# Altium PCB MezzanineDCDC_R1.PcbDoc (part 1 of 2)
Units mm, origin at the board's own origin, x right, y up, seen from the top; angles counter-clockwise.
Board outline 70 x 70 mm, 4 copper layers (Top Layer, GND 1, Signal, Bottom Layer), stack 1.554 mm thick; 95 components, 53 nets, 436 pads, 382 vias.
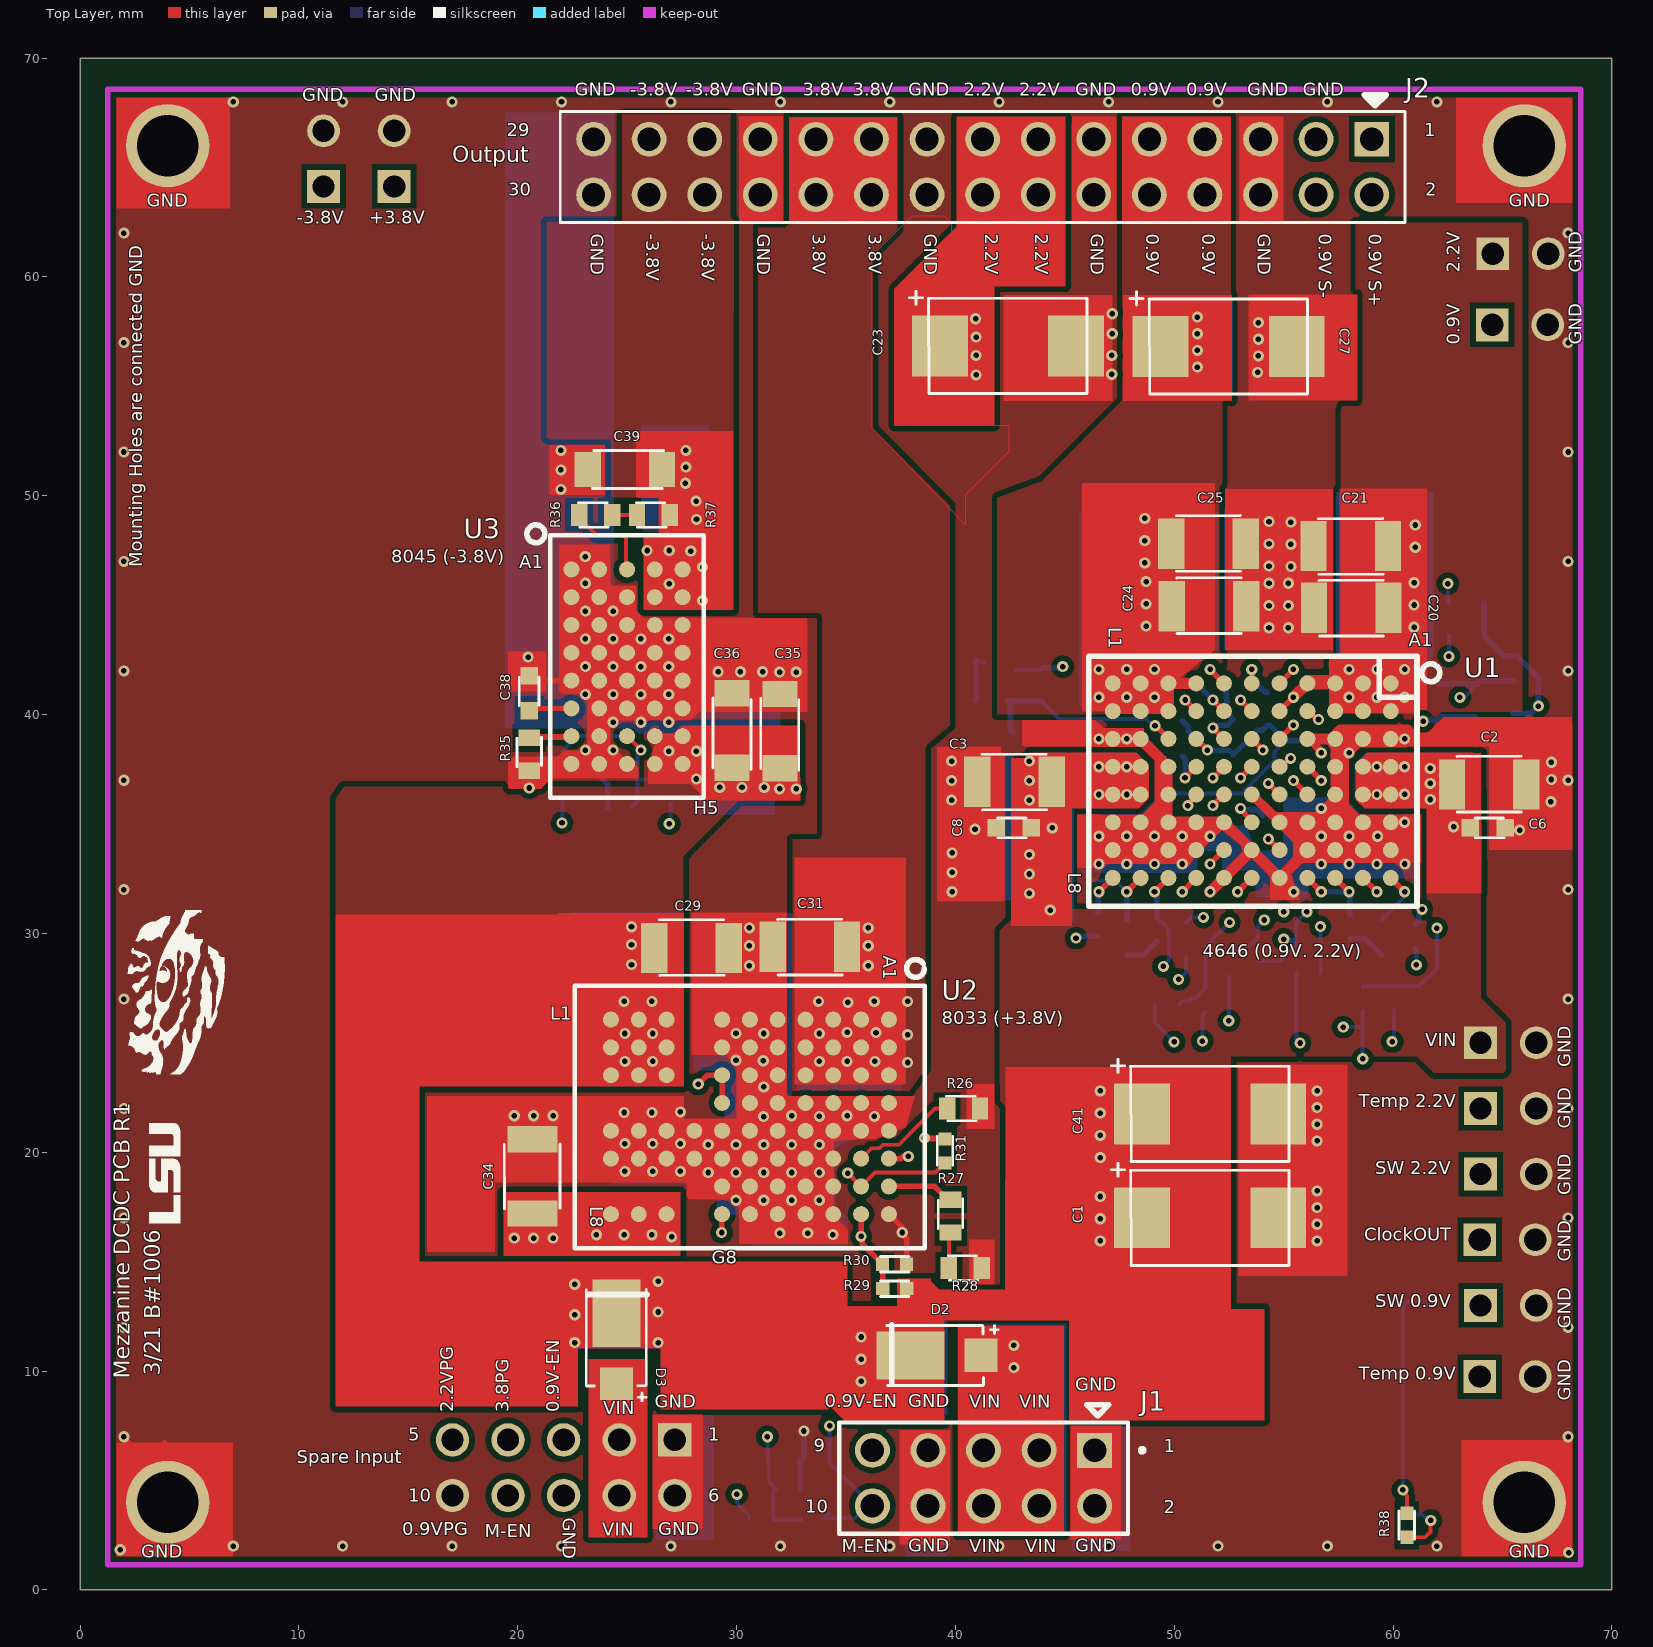
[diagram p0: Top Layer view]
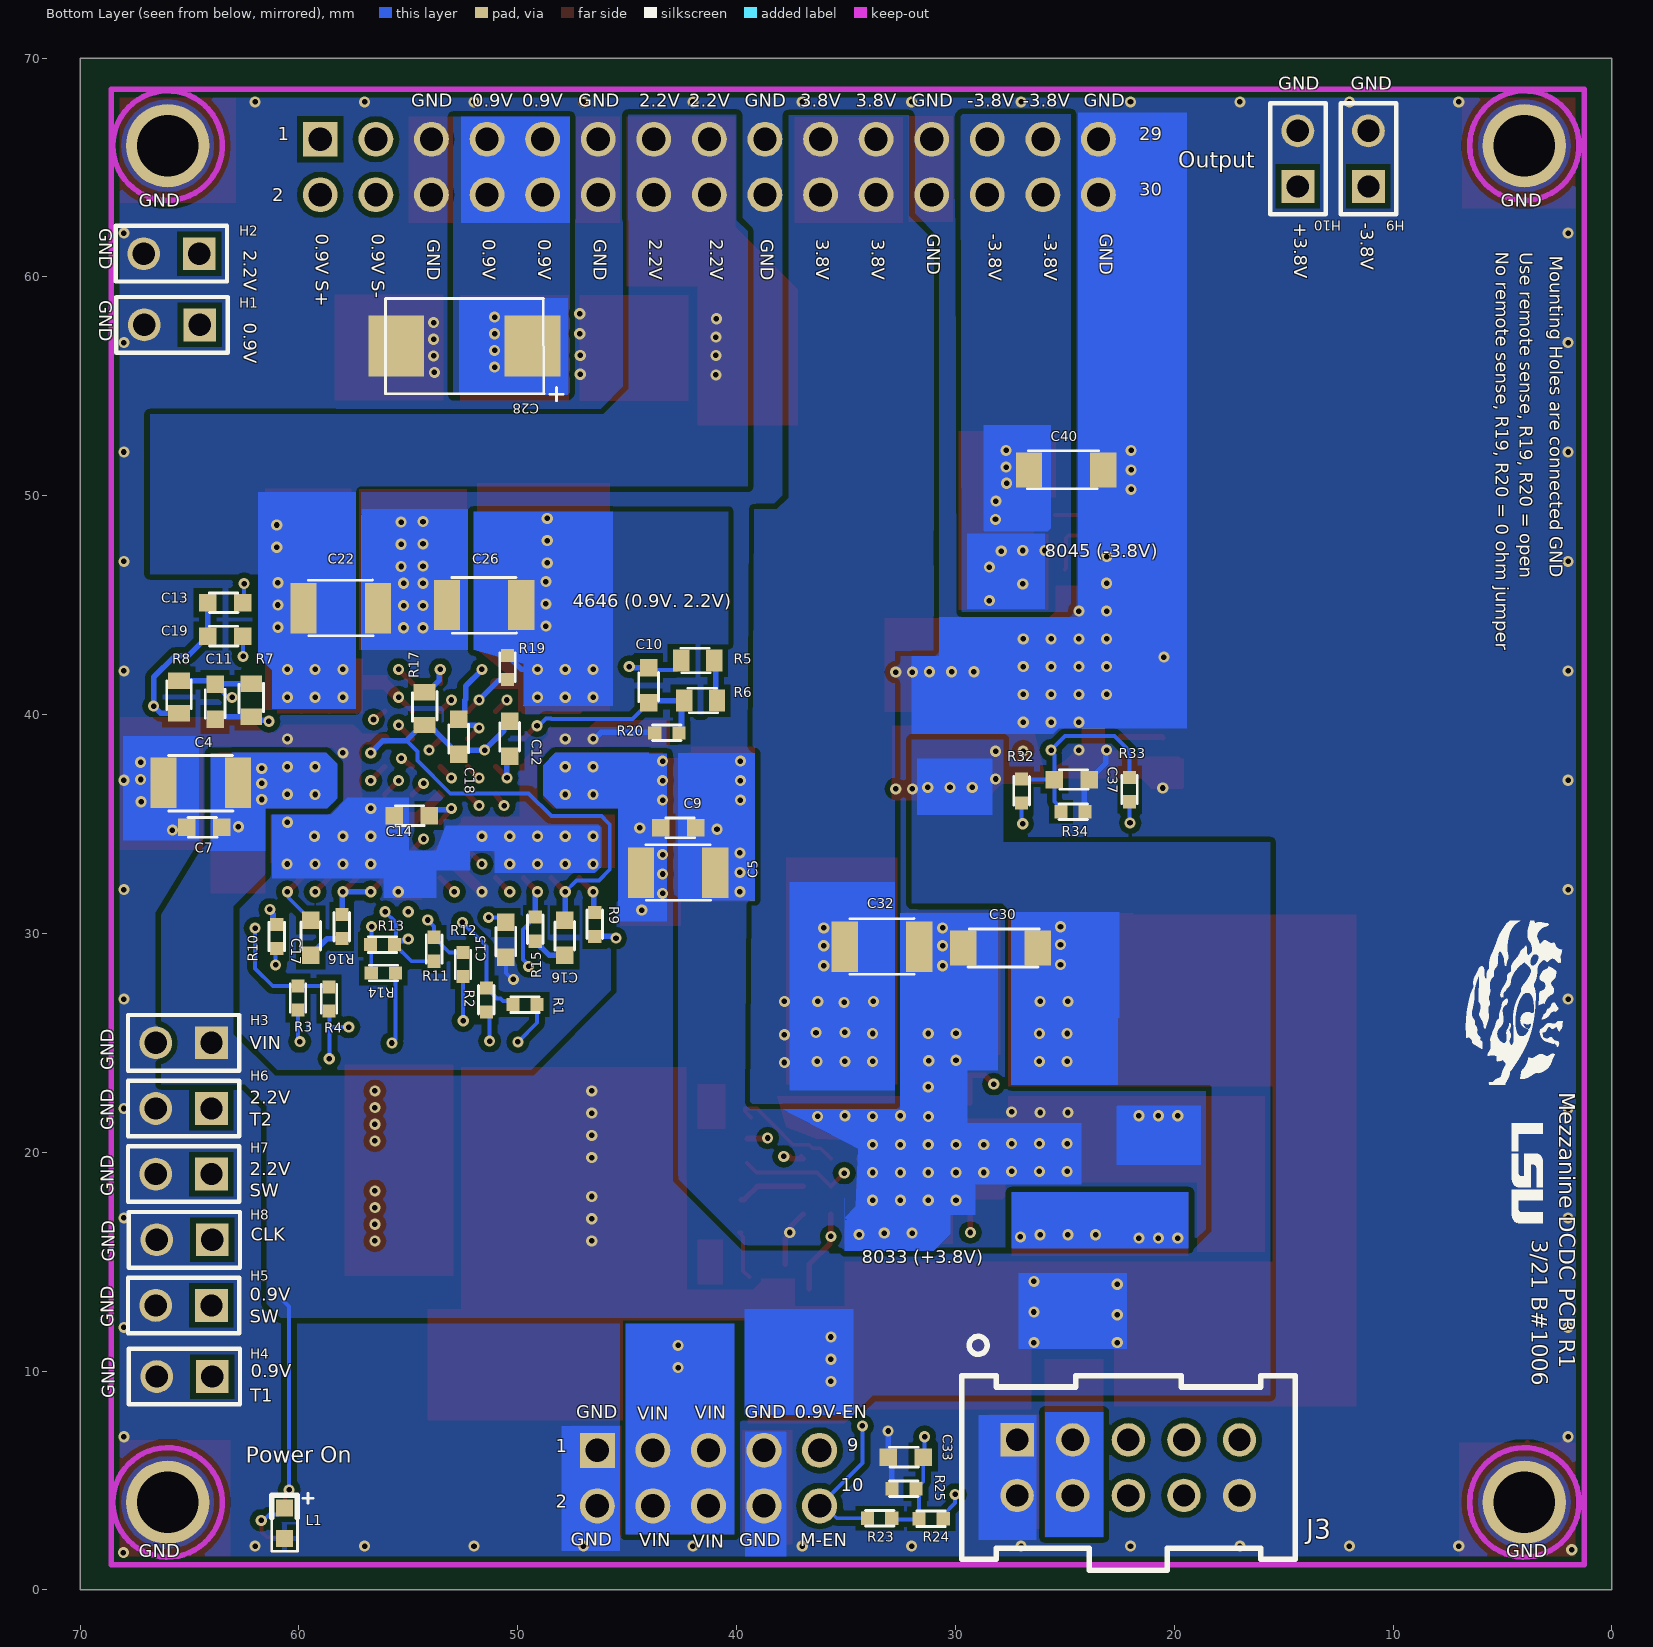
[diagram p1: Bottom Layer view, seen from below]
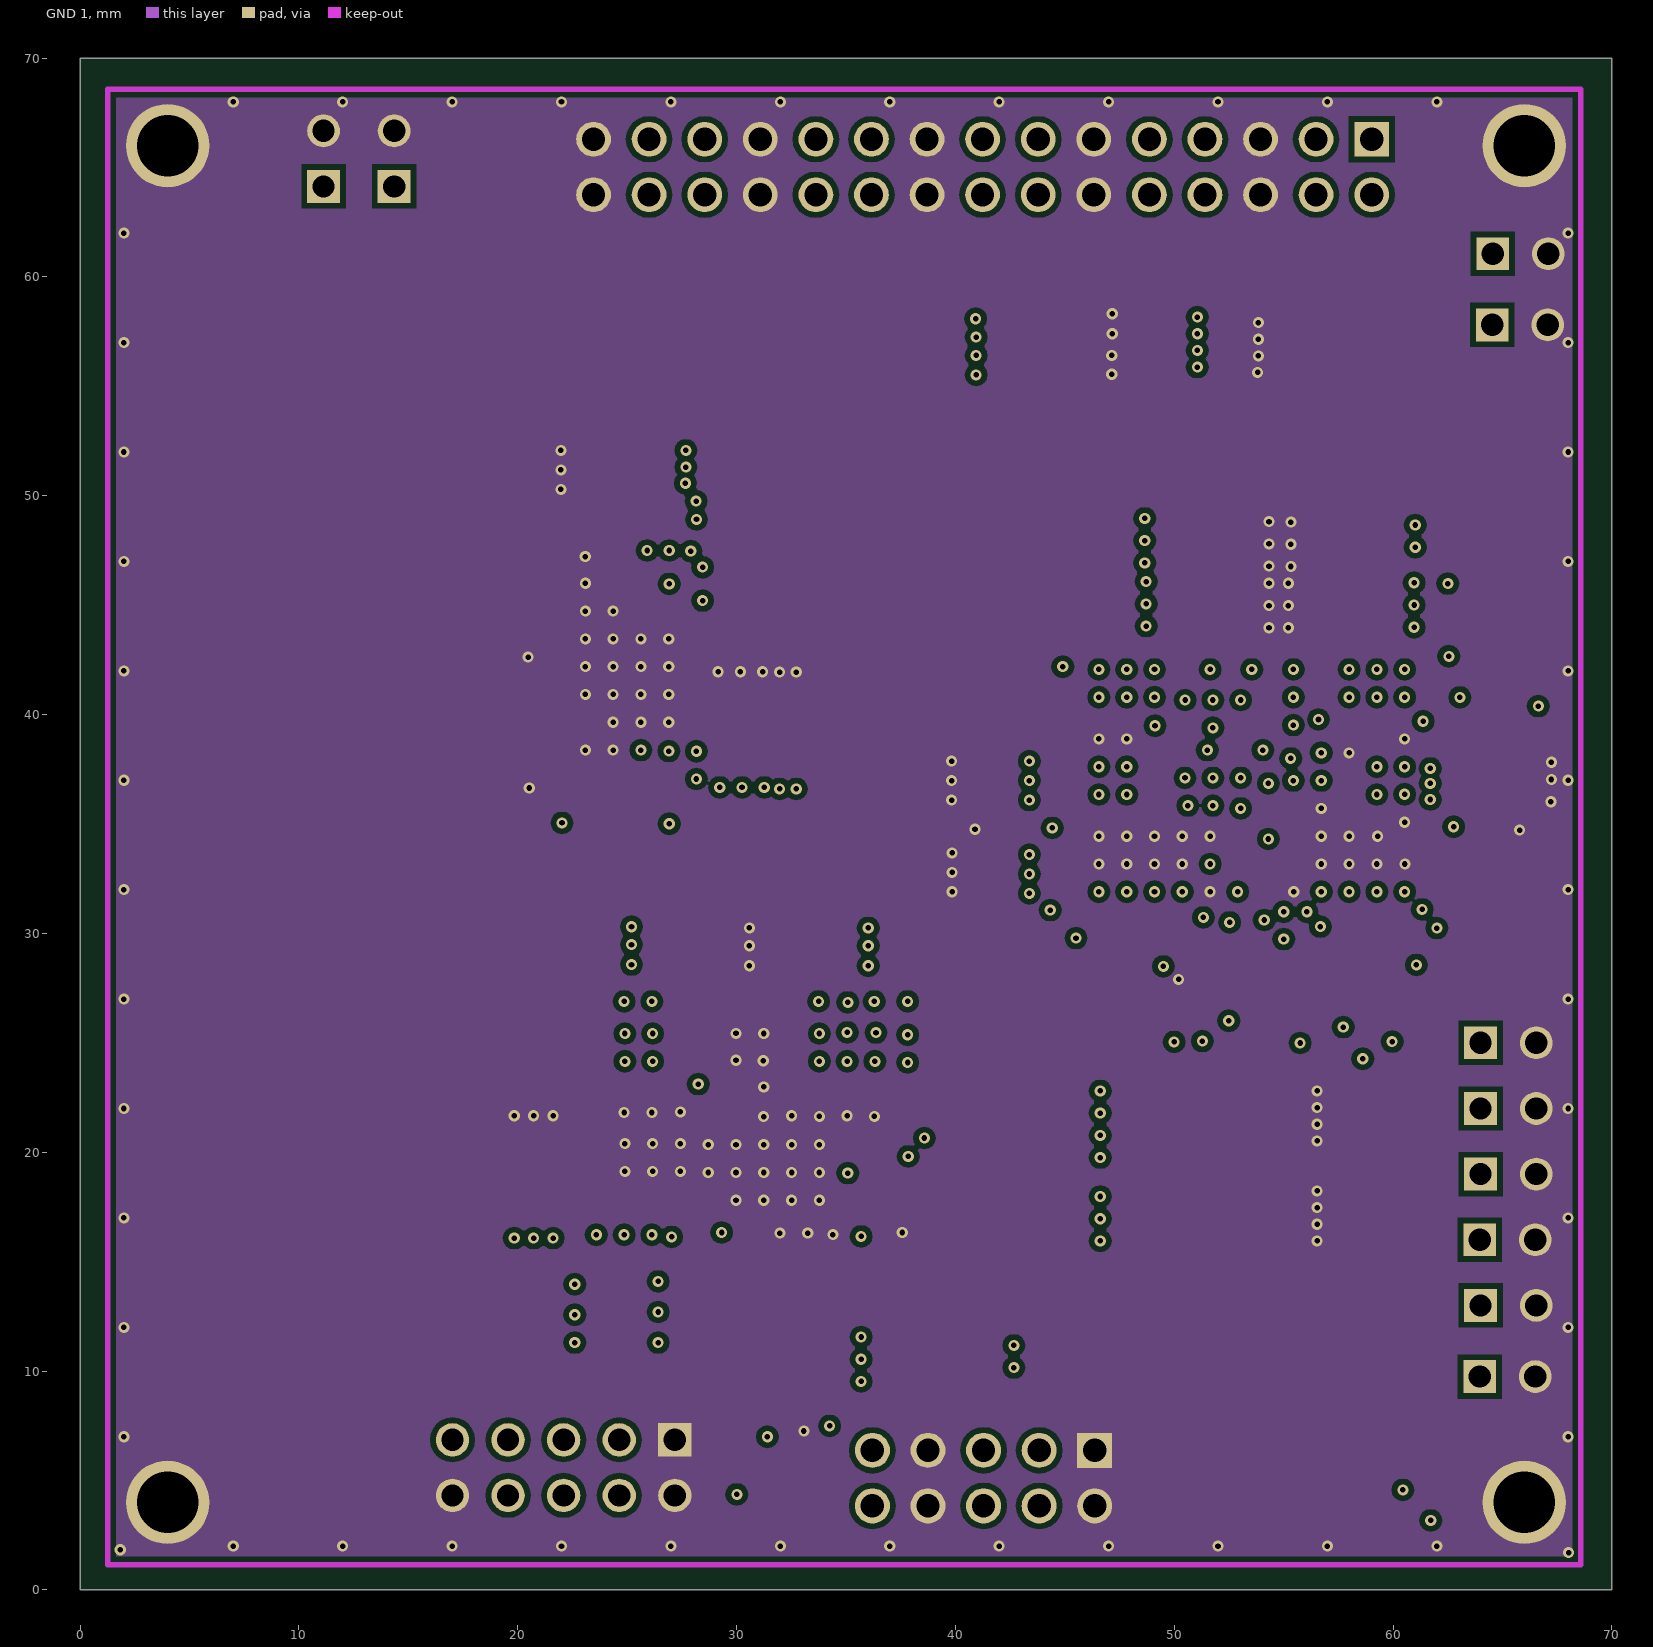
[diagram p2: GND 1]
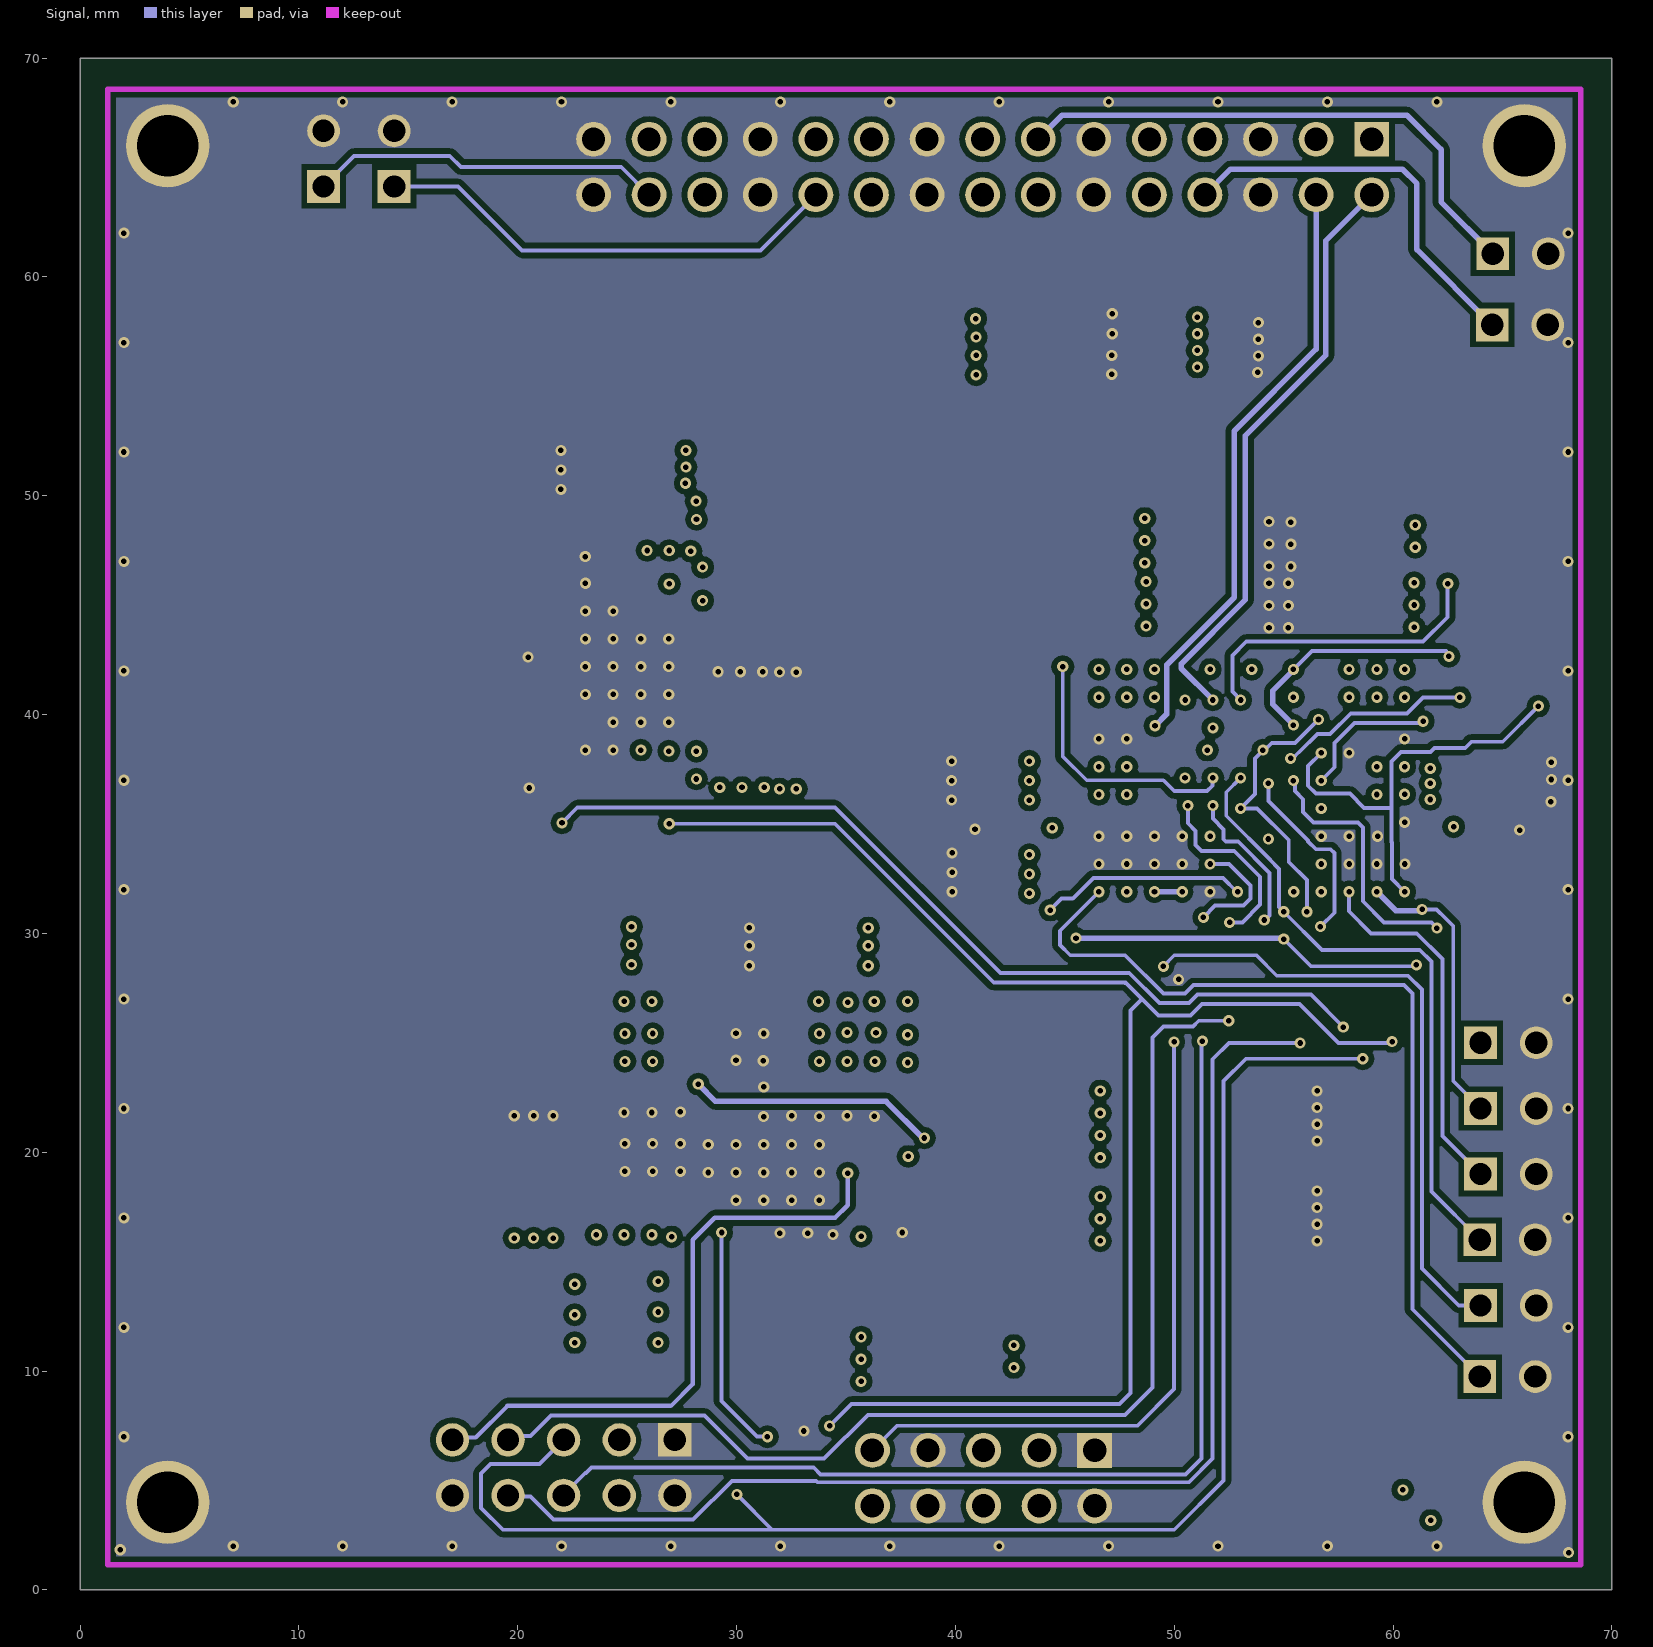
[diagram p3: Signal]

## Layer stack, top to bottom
Top Solder: solder mask 0.0102, Solder Resist, Dk 3.5
Top Layer: signal copper 0.0711
Dielectric 4: prepreg 0.1626, PP-006, Dk 4.1
GND 1: signal copper 0.0356
Dielectric 1: dielectric 1.016, FR-4, Dk 4.8
Signal: signal copper 0.0356
Dielectric 5: prepreg 0.1626, PP-006, Dk 4.1
Bottom Layer: signal copper 0.0711
Bottom Solder: solder mask 0.0102, Solder Resist, Dk 3.5

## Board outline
0,0 0,70 70,70 70,0

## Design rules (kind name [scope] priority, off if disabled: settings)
Clearance Clearance_1 [All] p1: gap=0.178 ignorepadtopadclearanceinfootprint=FALSE except(0.254: Arc-Fill Arc-Poly Arc-Region Track-Fill Track-Poly Track-Region SMDPad-Fill SMDPad-Poly SMDPad-Region THPad-Fill THPad-Poly THPad-Region Via-Fill Via-Poly Via-Region Fill-Fill Fill-Poly Fill-Region Fill-Hole Poly-Poly Poly-Region Poly-Hole Region-Region Region-Hole)
DiffPairsRouting [All] p1: maxlimit=0.254 minlimit=0.254 mostfreqgap=0.254 substack1={2EBA0CF7-B037-426B-A4ED-88C65EFE7A22} toplayer_{2eba0cf7-b037-426b-a4ed-88c65efe7a22}_minwidth=0.381 toplayer_{2eba0cf7-b037-426b-a4ed-88c65efe7a22}_maxwidth=0.381 toplayer_{2eba0cf7-b037-426b-a4ed-88c65efe7a22}_prefwidth=0.381 midlayer1_{2eba0cf7-b037-426b-a4ed-88c65efe7a22}_minwidth=0.381 midlayer1_{2eba0cf7-b037-426b-a4ed-88c65efe7a22}_maxwidth=0.381 midlayer1_{2eba0cf7-b037-426b-a4ed-88c65efe7a22}_prefwidth=0.381 midlayer4_{2eba0cf7-b037-426b-a4ed-88c65efe7a22}_minwidth=0.381 midlayer4_{2eba0cf7-b037-426b-a4ed-88c65efe7a22}_maxwidth=0.381 midlayer4_{2eba0cf7-b037-426b-a4ed-88c65efe7a22}_prefwidth=0.381 bottomlayer_{2eba0cf7-b037-426b-a4ed-88c65efe7a22}_minwidth=0.381 bottomlayer_{2eba0cf7-b037-426b-a4ed-88c65efe7a22}_maxwidth=0.381 bottomlayer_{2eba0cf7-b037-426b-a4ed-88c65efe7a22}_prefwidth=0.381 toplayer_minwidth=0.381 toplayer_maxwidth=0.381 toplayer_prefwidth=0.381 midlayer1_minwidth=0.381 midlayer1_maxwidth=0.381 midlayer1_prefwidth=0.381 midlayer4_minwidth=0.381 midlayer4_maxwidth=0.381 midlayer4_prefwidth=0.381 bottomlayer_minwidth=0.381 bottomlayer_maxwidth=0.381 bottomlayer_prefwidth=0.381 substack2={2E0713D7-164F-4516-AF41-5BA8AA759C5D} toplayer_{2e0713d7-164f-4516-af41-5ba8aa759c5d}_minwidth=0.381 toplayer_{2e0713d7-164f-4516-af41-5ba8aa759c5d}_maxwidth=0.381 toplayer_{2e0713d7-164f-4516-af41-5ba8aa759c5d}_prefwidth=0.381 midlayer1_{2e0713d7-164f-4516-af41-5ba8aa759c5d}_minwidth=0.381 midlayer1_{2e0713d7-164f-4516-af41-5ba8aa759c5d}_maxwidth=0.381 midlayer1_{2e0713d7-164f-4516-af41-5ba8aa759c5d}_prefwidth=0.381 midlayer4_{2e0713d7-164f-4516-af41-5ba8aa759c5d}_minwidth=0.381 midlayer4_{2e0713d7-164f-4516-af41-5ba8aa759c5d}_maxwidth=0.381 midlayer4_{2e0713d7-164f-4516-af41-5ba8aa759c5d}_prefwidth=0.381 bottomlayer_{2e0713d7-164f-4516-af41-5ba8aa759c5d}_minwidth=0.381 bottomlayer_{2e0713d7-164f-4516-af41-5ba8aa759c5d}_maxwidth=0.381 bottomlayer_{2e0713d7-164f-4516-af41-5ba8aa759c5d}_prefwidth=0.381 maxuncoupledlength=12.7
HoleSize [All] p1: absolutevalues=TRUE maxlimit=3.048 minlimit=0.127 maxpercent=80.000 minpercent=20.000
MinimumAnnularRing [IsVia] p1: minimumring=0.127
MinimumAnnularRing MinimumAnnularRing_1 [All] p2: minimumring=0.178
MinimumSolderMaskSliver [All] p1 off: minsoldermaskwidth=0.254
PolygonConnect [All] p1: connectstyle=Relief reliefconductorwidth=0.254 reliefentries=4 polygonreliefangle="90 Angle" airgapwidth=0.254
RoutingVias [All] p1: holewidth=0.711 width=1.27 viastyle="Through Hole" minholewidth=0.711 minwidth=1.27 maxholewidth=0.711 maxwidth=1.27
SilkToSilkClearance [All] p1 off: silktosilkclearance=0.254
SilkToSolderMaskClearance [IsPad] p1 off: minsilkscreentomaskgap=0.254 clearancetoexposedcopper=TRUE
SolderMaskExpansion [All] p1: expansion=0.127 istentingtop=FALSE
Width [All] p1: maxlimit=2.54 minlimit=0.178 preferedwidth=0.254 substack1={2EBA0CF7-B037-426B-A4ED-88C65EFE7A22} substack2={2E0713D7-164F-4516-AF41-5BA8AA759C5D}
25 further rules are at their usual default settings.

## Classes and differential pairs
component class U_MezzanineDCDC_4646: C1 C2 C3 C4 C5 C6 C7 C8 C9 C10 C11 C12 C13 C14 C15 C16 C17 C18 C19 C20 C21 C22 C23 C24 C25 C26 C27 C28 C41 H1 H2 H3 H4 H5 H6 H7 H8 R1 R2 R3 R4 R5 R6 R7 R8 R9 R10 R11 R12 R13 R14 R15 R16 R17 R19 R20 U1
component class U_MezzanineDCDC_8045: C35 C36 C37 C38 C39 C40 H9 R32 R33 R34 R35 R36 R37 U3
component class MezzanineDCDC_Overall: D2 D3 J1 J2 J3 L1 R38
component class U_MezzanineDCDC_8033: C29 C30 C31 C32 C33 C34 H10 R23 R24 R25 R26 R27 R28 R29 R30 R31 U2

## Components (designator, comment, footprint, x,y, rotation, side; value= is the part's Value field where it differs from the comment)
C1 "TAJE107K020RNJ" "CAP 2917 TANTALUM POLARIZED TAJE107K020RNJ" 48.53,17 r0 top locked value="100uF 20V"
C2 "GRM32ER61E226KE15L" "CAP 1210 MURATA" 62.691,36.805 r0 top locked value="22uF 25V"
C3 "GRM32ER61E226KE15L" "CAP 1210 MURATA" 44.398,36.934 r180 top locked value="22uF 25V"
C4 "GRM32ER61E226KE15L" "CAP 1210 MURATA" 62.789,36.881 r0 bottom locked value="22uF 25V"
C5 "GRM32ER61E226KE15L" "CAP 1210 MURATA" 44.37,32.766 r180 bottom locked value="22uF 25V"
C6 "GCM188R71E105KA64D" "CAP 0603 TDK" 63.525,34.823 r0 top locked value="1uF 25V"
C7 "GCM188R71E105KA64D" "CAP 0603 TDK" 63.526,34.849 r0 bottom locked value="1uF 25V"
C8 "C1608X7R1E224K080AC" "CAP 0603 TDK" 43.459,34.823 r180 top locked value="0.22uF 25V"
C9 "C1608X7R1E224K080AC" "CAP 0603 TDK" 43.459,34.823 r180 bottom locked value="0.22uF 25V"
C10 "opt" "CAP 0603 TDK" 44.018,42.138 r270 bottom locked
C11 "opt" "CAP 0603 TDK" 63.83,41.376 r270 bottom locked
C12 "0603YC273KAT2A" "CAP 0603 TDK" 50.368,38.1 r90 bottom locked value=27nF
C13 "0603YC273KAT2A" "CAP 0603 TDK" 62.56,45.11 r0 bottom locked value=27nF
C14 "C1608X5R1C475K080AC" "CAP 0603 TDK" 54.051,35.382 r0 bottom locked value=opt
C15 "C1608X5R1C475K080AC" "CAP 0603 TDK" 50.546,30.505 r270 bottom locked value=4.7uF
C16 "opt" "CAP 0603 TDK" 47.854,29.007 r90 bottom locked
C17 "opt" "CAP 0603 TDK" 59.461,29.007 r90 bottom locked
C18 "0603YC101KAT2A" "CAP 0603 TDK" 52.705,39.776 r270 bottom locked value=100pF
C19 "0603YC101KAT2A" "CAP 0603 TDK" 62.56,43.586 r0 bottom locked value=100pF
C20 "GRM32ER60J107ME20K" "CAP 1210 Murata" 59.792,44.882 r180 top locked value=100uF
C21 "GRM32ER60J107ME20K" "CAP 1210 Murata" 59.766,47.701 r180 top locked value=100uF
C22 "GRM32ER60J107ME20K" "CAP 1210 Murata" 59.792,44.856 r180 bottom locked value=100uF
C23 "4TPE470MCL" "CAP 2917 Tantalum Polarized" 39.294,56.845 r0 top value=470uF
C24 "GRM32ER60J107ME20K" "CAP 1210 Murata" 49.889,44.958 r0 top locked value=100uF
C25 "GRM32ER60J107ME20K" "CAP 1210 Murata" 49.864,47.803 r0 top locked value=100uF
C26 "GRM32ER60J107ME20K" "CAP 1210 Murata" 49.838,45.009 r0 bottom locked value=100uF
C27 "4TPE470MCL" "CAP 2917 Tantalum Polarized" 49.378,56.82 r0 top locked value=470uF
C28 "4TPE470MCL" "CAP 2917 Tantalum Polarized" 49.33,56.843 r0 bottom locked value=470uF
C29 "GRM32ER61E226KE15L" "CAP 1210 MURATA" 26.242,29.337 r0 top locked value="22uF 25V"
C30 "UMK316BJ475KL-T" "CAP 1206 TDK" 26.242,29.337 r0 bottom locked value="4.7uF 50V"
C31 "LMK325BJ107MM-T" "CAP 1210 MURATA" 35.05,29.388 r180 top locked value="100uF 10V"
C32 "OPT" "CAP 1210 MURATA" 35.054,29.388 r180 bottom locked value=opt
C33 "C1608X7R1E224K080AC" "CAP 0603 TDK" 31.471,6.071 r0 bottom locked value="0.22uF 25V"
C34 "GRM32ER71H106KA12L" "CAP 1210 MURATA" 20.677,17.196 r90 top locked value=10uF
C35 "C3216X5R1E476M160AC" "CAP 1206 TDK" 31.979,37.545 r90 top locked value="47uF 25V"
C36 "UMK316BJ475KL-T" "CAP 1206 TDK" 29.794,37.57 r90 top locked value="4.7uF 50V"
C37 "C1608X7R1E104K080AA" "CAP 0603 TDK" 25.476,37.033 r180 bottom locked value="0.1uF 25V"
C38 "C1608X7R1E104K080AA" "CAP 0603 TDK" 20.523,40.183 r90 top locked value=0.1uF
C39 "12066D476MAT4A" "CAP 1206 TDK 2.3 Height" 26.594,51.206 r180 top locked value="47uF 6.3V"
C40 "opt" "CAP 1206 TDK 2.3 Height" 26.641,51.181 r180 bottom locked
C41 "TAJE107K020RNJ" "CAP 2917 TANTALUM POLARIZED TAJE107K020RNJ" 48.53,21.75 r0 top locked value="100uF 20V"
D2 "V8PAL50-M3/I" "SCHOTTKY DIODE V8PAL50-M3/I" 37.953,10.719 r0 top locked
D3 "V8PAL50-M3/I" "SCHOTTKY DIODE V8PAL50-M3/I" 24.511,12.643 r270 top locked
H1 "Header" "HEADER 2PIN" 64.53,57.81 r180 bottom locked
H2 "Header" "HEADER 2PIN" 64.555,61.062 r180 bottom locked
H3 "Header" "HEADER 2PIN" 64,25 r180 bottom locked
H4 "Header" "HEADER 2PIN" 63.96,9.75 r180 bottom locked
H5 "Header" "HEADER 2PIN" 64,13 r180 bottom locked
H6 "Header" "HEADER 2PIN" 64,22 r180 bottom locked
H7 "Header" "HEADER 2PIN" 64,19 r180 bottom locked
H8 "Header" "HEADER 2PIN" 63.96,16 r180 bottom locked
H9 "Header" "HEADER 2PIN" 11.125,64.135 r270 bottom locked
H10 "Header" "HEADER 2PIN" 14.351,64.135 r270 bottom locked
J1 "Samtec IPT1-105-01-L-D" SAMTEC_IPT1-105-01-L-D 46.367,6.379 r180 top locked
J2 "Samtec IPT1-115-01-L-D" IPT1-115-01-L-D 59.023,66.292 r180 top locked
J3 "Samtec IPL1-105-01-L-D" IPL1-105-01-L-D 27.178,6.858 r180 bottom locked
L1 "LTST-C191KRKT" LED 60.655,3.734 r180 bottom locked
R1 "CRCW04020000ZSTD" "RESISTOR ERJ2G/CRCW 0402" 50.216,26.746 r180 bottom locked value="0 ohm jumper"
R2 "opt" "RESISTOR ERJ2G/CRCW 0402" 51.435,27.508 r270 bottom locked
R3 "CRCW04020000ZSTD" "RESISTOR ERJ2G/CRCW 0402" 60.046,27.592 r270 bottom locked value="0 ohm jumper"
R4 "opt" "RESISTOR ERJ2G/CRCW 0402" 58.623,27.559 r270 bottom locked
R5 "ERA-3AEB124V" "RESISTOR 0603 - ERJ" 41.021,42.469 r0 bottom locked value="120k 0.1%"
R6 "ERA-3AEB8250V" "RESISTOR 0603 - ERJ" 42.394,40.64 r180 bottom locked value="825 0.1%"
R7 "ERA-3AEB2262V" "RESISTOR 0603 - ERJ" 62.179,39.903 r90 bottom locked value="22.6k 0.1%"
R8 "ERA-3AEB1652V" "RESISTOR 0603 - ERJ" 65.481,40.054 r90 bottom locked value="16.5k 0.1%"
R9 "ERA-2AEB4992X" "RESISTOR ERJ2G/CRCW 0402" 46.482,30.963 r270 bottom locked value=50k
R10 "ERA-2AEB4992X" "RESISTOR ERJ2G/CRCW 0402" 61.011,30.404 r270 bottom locked value=50k
R11 "ERJ-2GEJ103X" "RESISTOR ERJ2G/CRCW 0402" 53.823,29.827 r270 bottom locked value=10k
R12 "ERJ-2GEJ102X" "RESISTOR ERJ2G/CRCW 0402" 52.502,28.034 r90 bottom locked value=1k
R13 "ERJ-2GEJ103X" "RESISTOR ERJ2G/CRCW 0402" 56.726,29.489 r180 bottom locked value=10k
R14 "ERJ-2GEJ102X" "RESISTOR ERJ2G/CRCW 0402" 55.593,28.194 r0 bottom locked value=1k
R15 "opt" "RESISTOR ERJ2G/CRCW 0402" 49.2,29.642 r90 bottom locked
R16 "opt" "RESISTOR ERJ2G/CRCW 0402" 58.039,29.761 r90 bottom locked
R17 "ERA-3AEB333V" "RESISTOR 0603 - ERJ" 54.254,39.522 r90 bottom locked value="33k 0.1%"
R19 "opt" "RESISTOR ERJ2G/CRCW 0402" 50.47,42.705 r270 bottom locked
R20 "opt" "RESISTOR ERJ2G/CRCW 0402" 43.739,39.167 r180 bottom locked
R23 "ERJ-U02F1502X" "RESISTOR ERJ2G/CRCW 0402" 32.911,3.277 r0 bottom locked value=15k
R24 "opt" "RESISTOR ERJ2G/CRCW 0402" 31.656,3.251 r180 bottom locked
R25 "opt" "RESISTOR ERJ2G/CRCW 0402" 32.901,4.623 r180 bottom locked
R26 "ERJ-PB3B1782V" "RESISTOR 0603 - ERJ" 41.124,21.996 r180 top locked value="17.8k 0.1%"
R27 "ERA-3AEB134V" "RESISTOR 0603 - ERJ" 39.778,16.332 r90 top locked value="130k 0.1%"
R28 "ERA-3AEB8250V" "RESISTOR 0603 - ERJ" 41.2,14.707 r180 top locked value="825 0.1%"
R29 "opt" "RESISTOR ERJ2G/CRCW 0402" 36.678,13.767 r0 top locked
R30 "ERJ-2GEJ103X" "RESISTOR ERJ2G/CRCW 0402" 37.77,14.884 r180 top locked value=10k
R31 "ERJ-2RKF1003X" "RESISTOR ERJ2G/CRCW 0402" 39.522,20.607 r270 top locked value=100k
R32 "CRCW04024K99FKED" "RESISTOR ERJ2G/CRCW 0402" 26.975,37.059 r270 bottom locked value=4.99k
R33 "opt" "RESISTOR ERJ2G/CRCW 0402" 22.047,37.117 r270 bottom locked
R34 "opt" "RESISTOR ERJ2G/CRCW 0402" 24.071,35.56 r0 bottom locked
R35 "ERJ-PB3B6492V" "RESISTOR 0603 - ERJ" 20.523,37.44 r90 top locked value="64.9k 0.1%"
R36 "ERA-3AEB4532V" "RESISTOR 0603 - ERJ" 24.309,49.124 r180 top locked value="45.3k 0.1%"
R37 "ERA-3AEB301V" "RESISTOR 0603 - ERJ" 26.951,49.124 r180 top locked value="300 0.1%"
R38 "ERJ-2GEJ102X" "RESISTOR ERJ2G/CRCW 0402" 60.63,3.505 r270 top locked value=1k
U1 "LTM4646IY_REV_0" LTM4646 53.543,36.982 r270 top locked net-tie
U2 "LTM8033EY#PBF" "LTM8033 BGA" 30.609,21.615 r270 top locked
U3 "LTM8045EY#PBF" LTM8045 24.994,42.189 r0 top locked

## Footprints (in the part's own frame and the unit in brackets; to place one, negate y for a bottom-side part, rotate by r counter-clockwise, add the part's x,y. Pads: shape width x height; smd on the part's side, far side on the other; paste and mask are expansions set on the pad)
"CAP 0603 TDK" [mm]
  rect 0.8x0.8 smd: 1(0,0) 2(1.6,0)
  silkscreen extent 0.22,-0.45 1.54,0.45, body extent 0,-0.4 1.6,0.4, height 0.9
"CAP 1206 TDK" [mm]
  rect 1.2x1.6 smd: 1(0,0) 2(3.4,0)
  silkscreen extent -0.08,-0.86 3.19,0.87, body extent 0,-0.8 3.2,0.8, height 1.9
"CAP 1206 TDK 2.3 Height" [mm]
  rect 1.2x1.6 smd: 1(0,0) 2(3.4,0)
  silkscreen extent -0.08,-0.86 3.19,0.87, body extent 0,-0.84 3.2,0.84, height 2.3
"CAP 1210 MURATA" [mm]
  rect 1.2x2.3 smd: 1(0,0) 2(3.4,0)
  silkscreen extent 0.23,-1.26 3.18,1.29, body extent 0.01,-1.25 3.2,1.25, height 2.7
"CAP 1210 Murata" [mm]
  rect 1.2x2.3 smd: 1(0,0) 2(3.4,0)
  silkscreen extent 0.23,-1.26 3.18,1.29, body extent 0.01,-1.25 3.2,1.25, height 2.7
"CAP 2917 Tantalum Polarized" [mm]
  rect 2.55x2.77 smd: 1(0,0) 2(6.22,0)
  silkscreen extent -1.4,-2.18 6.72,2.5, body extent -0.54,-2.14 6.74,2.18, height 3
"CAP 2917 TANTALUM POLARIZED TAJE107K020RNJ" [mm]
  rect 2.55x2.77 smd: 1(0,0) 2(6.22,0)
  silkscreen extent -1.4,-2.18 6.72,2.5, body extent -0.54,-2.14 6.74,2.18, height 4.3
"HEADER 2PIN" [mm]
  rect 1.5x1.5 hole 1.016: 1(0,0)
  round 1.5 hole 1.016: 2(-2.54,0)
  silkscreen extent -3.81,-1.27 1.27,1.27, body extent -3.73,-1.17 1.27,1.18, height 8.38
IPL1-105-01-L-D [mil] "Discrete wire header"
  rect 60x60 hole 40 mask+3: 1(0,0)
  round 60 hole 40 mask+3: 2(100,0) 3(200,0) 4(300,0) 6(0,-100) 7(100,-100) 8(200,-100) 9(300,-100) 10(400,-100)
  round 60 hole 40: 5(400,0)
  silkscreen extent -100,-235 500,115, body extent -95,-215 482,115, height 320
IPT1-115-01-L-D [mm]
  rect 1.59x1.59 hole 1.06: 1(0,0)
  round 1.59 hole 1.06: 2(0,2.54) 3(2.54,0) 4(2.54,2.54) 5(5.08,0) 6(5.08,2.54) 7(7.62,0) 8(7.62,2.54) 9(10.16,0) 10(10.16,2.54) 11(12.7,0) 12(12.7,2.54) 13(15.24,0) 14(15.24,2.54) 15(17.78,0) 16(17.78,2.54) 17(20.32,0) 18(20.32,2.54) 19(22.86,0) 20(22.86,2.54) 21(25.4,0) 22(25.4,2.54) 23(27.94,0) 24(27.94,2.54) 25(30.48,0) 26(30.48,2.54) 27(33.02,0) 28(33.02,2.54) 29(35.56,0) 30(35.56,2.54)
  silkscreen extent -1.52,-1.9 37.08,3.81, body extent -1.47,-1.28 37.11,3.78, height 6.35
LED [mil]
  rect 30x30 smd: 1(0,0.5) 2(0,-54.5)
  silkscreen extent -23,-78 51,27, body extent -16,-62 16,0, height 26
LTM4646 [mm]
  round 0.73 smd: A1(-4.445,6.35) A2(-3.175,6.35) A3(-1.905,6.35) A4(-0.635,6.35) A5(0.635,6.35) A6(1.905,6.35) A7(3.175,6.35) A8(4.445,6.35) B1(-4.445,5.08) B2(-3.175,5.08) B3(-1.905,5.08) B4(-0.635,5.08) B5(0.635,5.08) B6(1.905,5.08) B7(3.175,5.08) B8(4.445,5.08) C1(-4.445,3.81) C2(-3.175,3.81) C3(-1.905,3.81) C4(-0.635,3.81) C5(0.635,3.81) C6(1.905,3.81) C7(3.175,3.81) C8(4.445,3.81) D1(-4.445,2.54) D2(-3.175,2.54) D3(-1.905,2.54) D4(-0.635,2.54) D5(0.635,2.54) D6(1.905,2.54) D7(3.175,2.54) D8(4.445,2.54) E1(-4.445,1.27) E2(-3.175,1.27) E3(-1.905,1.27) E4(-0.635,1.27) E5(0.635,1.27) E6(1.905,1.27) E7(3.175,1.27) E8(4.445,1.27) F1(-4.445,0) F2(-3.175,0) F3(-1.905,0) F4(-0.635,0) F5(0.635,0) F6(1.905,0) F7(3.175,0) F8(4.445,0) G1(-4.445,-1.27) G2(-3.175,-1.27) G3(-1.905,-1.27) G4(-0.635,-1.27) G5(0.635,-1.27) G6(1.905,-1.27) G7(3.175,-1.27) G8(4.445,-1.27) H1(-4.445,-2.54) H2(-3.175,-2.54) H3(-1.905,-2.54) H4(-0.635,-2.54) H5(0.635,-2.54) H6(1.905,-2.54) H7(3.175,-2.54) H8(4.445,-2.54) J1(-4.445,-3.81) J2(-3.175,-3.81) J3(-1.905,-3.81) J4(-0.635,-3.81) J5(0.635,-3.81) J6(1.905,-3.81) J7(3.175,-3.81) J8(4.445,-3.81) K1(-4.445,-5.08) K2(-3.175,-5.08) K3(-1.905,-5.08) K4(-0.635,-5.08) K5(0.635,-5.08) K6(1.905,-5.08) K7(3.175,-5.08) K8(4.445,-5.08) L1(-4.445,-6.35) L2(-3.175,-6.35) L3(-1.905,-6.35) L4(-0.635,-6.35) L5(0.635,-6.35) L6(1.905,-6.35) L7(3.175,-6.35) L8(4.445,-6.35)
  Top Layer lines w0.508: -1.905,2.54 -1.905,3.81
  silkscreen extent -5.69,-7.45 5.74,7.55, body extent -5.59,-7.49 5.59,7.49, height 5.01
"LTM8033 BGA" [mm]
  round 0.73 smd: A1(-4.445,6.35) A2(-3.175,6.35) A3(-1.905,6.35) A4(-0.635,6.35) A5(0.635,6.35) A6(1.905,6.35) A7(3.175,6.35) A8(4.445,6.35) B1(-4.445,5.08) B2(-3.175,5.08) B3(-1.905,5.08) B4(-0.635,5.08) B5(0.635,5.08) B6(1.905,5.08) B7(3.175,5.08) B8(4.445,5.08) C1(-4.445,3.81) C2(-3.175,3.81) C3(-1.905,3.81) C4(-0.635,3.81) C5(0.635,3.81) C6(1.905,3.81) C7(3.175,3.81) C8(4.445,3.81) D1(-4.445,2.54) D2(-3.175,2.54) D3(-1.905,2.54) D4(-0.635,2.54) D5(0.635,2.54) D6(1.905,2.54) D7(3.175,2.54) D8(4.445,2.54) E1(-4.445,1.27) E2(-3.175,1.27) E3(-1.905,1.27) E4(-0.635,1.27) E5(0.635,1.27) E6(1.905,1.27) E7(3.175,1.27) E8(4.445,1.27) F1(-4.445,0) F2(-3.175,0) F3(-1.905,0) F4(-0.635,0) F5(0.635,0) F6(1.905,0) F7(3.175,0) F8(4.445,0) G1(-4.445,-1.27) G2(-3.175,-1.27) G3(-1.905,-1.27) G4(-0.635,-1.27) G5(0.635,-1.27) G6(1.905,-1.27) G7(3.175,-1.27) G8(4.445,-1.27) H5(0.635,-2.54) H6(1.905,-2.54) J1(-4.445,-3.81) J2(-3.175,-3.81) J3(-1.905,-3.81) J5(0.635,-3.81) J6(1.905,-3.81) J8(4.445,-3.81) K1(-4.445,-5.08) K2(-3.175,-5.08) K3(-1.905,-5.08) K5(0.635,-5.08) K6(1.905,-5.08) K8(4.445,-5.08) L1(-4.445,-6.35) L2(-3.175,-6.35) L3(-1.905,-6.35) L5(0.635,-6.35) L6(1.905,-6.35) L8(4.445,-6.35)
  silkscreen extent -6,-8 6,8, body extent -5.59,-7.49 5.59,7.49, height 4.92
LTM8045 [mm] "DCDC Converter"
  round 0.73 smd: A1(-2.54,4.445) A2(-1.27,4.445) A3(0,4.445) A4(1.27,4.445) A5(2.54,4.445) B1(-2.54,3.175) B2(-1.27,3.175) B3(0,3.175) B4(1.27,3.175) B5(2.54,3.175) C1(-2.54,1.905) C2(-1.27,1.905) C3(0,1.905) C4(1.27,1.905) C5(2.54,1.905) D1(-2.54,0.635) D2(-1.27,0.635) D3(0,0.635) D4(1.27,0.635) D5(2.54,0.635) E1(-2.54,-0.635) E2(-1.27,-0.635) E3(0,-0.635) E4(1.27,-0.635) E5(2.54,-0.635) F1(-2.54,-1.905) F2(-1.27,-1.905) F3(0,-1.905) F4(1.27,-1.905) F5(2.54,-1.905) G1(-2.54,-3.175) G2(-1.27,-3.175) G3(0,-3.175) G4(1.27,-3.175) G5(2.54,-3.175) H1(-2.54,-4.445) H2(-1.27,-4.445) H3(0,-4.445) H4(1.27,-4.445) H5(2.54,-4.445)
  silkscreen extent -3.5,-6 3.5,6, body extent -3.35,-5.79 3.38,5.85, height 4.92
"RESISTOR 0603 - ERJ" [mm]
  rect 0.75x1 smd: 1(0,0) 2(1.5,0)
  silkscreen extent 0.18,-0.56 1.53,0.56, body extent 0,-0.4 1.6,0.4, height 0.55
"RESISTOR ERJ2G/CRCW 0402" [mm]
  rect 0.6x0.6 smd: 1(0,0) 2(1.1,0)
  silkscreen extent -0.11,-0.36 1.19,0.36, body extent 0,-0.25 1,0.25, height 0.4
SAMTEC_IPT1-105-01-L-D [mil]
  rect 63x63 hole 42: 01(0,0)
  round 63 hole 42: 02(0,100) 03(100,0) 04(100,100) 05(200,0) 06(200,100) 07(300,0) 08(300,100) 09(400,0) 10(400,100)
  silkscreen extent -89,-50 460,150, body extent -56,-47 459,152, height 250
"SCHOTTKY DIODE V8PAL50-M3/I" [mm]
  rect 3.1x2.2 smd: 1(0,0)
  rect 1.5x1.52 smd: 2(3.22,0)
  silkscreen extent -1.09,-1.38 4,1.39, body extent -0.98,-1.38 3.36,1.35, height 1

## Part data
C1 C41: library part "Capacitor 2917 TAJE107K020RNJ", "100µF Molded Tantalum Capacitors 20V 2917 (7343 Metric) 400mOhm"
C2 C3 C4 C5 C29: library part "Capacitor 1210", "22µF ±10% 25V Ceramic Capacitor X5R 1210 (3225 Metric)"
C6 C7: library part "Capacitor 0603 TDK", "1µF ±10% 25V Ceramic Capacitor X7R 0603 (1608 Metric)"
C8 C9 C33: library part "Capacitor 0603 TDK", "CAP CER 0.22UF 25V X7R 0603"
C10 C11 C16 C17: library part "Capacitor 0603 TDK", "Capacitor 0603"
C12 C13: library part "Capacitor 0603 TDK", "0.027µF ±10% 16V Ceramic Capacitor X7R 0603 (1608 Metric)"
C14 C15: library part "Capacitor 0603 TDK", "CAP CER 4.7UF 16V X5R 0603"
C18 C19: library part "Capacitor 0603 TDK", "100pF ±10% 16V Ceramic Capacitor X7R 0603 (1608 Metric)"
C20 C21 C22 C24 C25 C26: library part "Capacitor 1210", "100µF ±20% 6.3V Ceramic Capacitor X5R 1210 (3225 Metric)"
C23 C27 C28: library part "Capacitor 2917 Panasonic", "470µF Molded Tantalum Polymer Capacitor 4V 2917 (7343 Metric) 12mOhm @ 100kHz"
C30 C36: library part "Capacitor 1206", "4.7µF ±10% 50V Ceramic Capacitor X5R 1206 (3216 Metric)"
C31: library part "Capacitor 1210", "CAP CER 100UF 10V X5R 1210"
C32: library part "Capacitor 1210", "Cap 1210"
C34: library part "Capacitor 1210", "CAP CER 10UF 50V X7R 1210"
C35: library part "Capacitor 1206", "47µF ±20% 25V Ceramic Capacitor X5R 1206 (3216 Metric)"
C37 C38: library part "Capacitor 0603 TDK", "CAP CER 0.1UF 25V X7R 0603"
C39: library part "Capacitor 1206 2.3mmHeight", "47µF ±20% 6.3V Ceramic Capacitor X5R 1206 (3216 Metric)"
C40: library part "Capacitor 1206 2.3mmHeight"
D2 D3: library part "Schotkky Diode", "Diode Schottky 50V 4A Surface Mount DO-221BC (SMPA)"
H1 H2 H3 H4 H5 H6 H7 H8 H9 H10: library part "Header - 2Pin", "Connector Header Through Hole 2 position 0.100\" (2.54mm)"
J1: "CONN HEADER VERT 10POS 2.54MM"
J2: "15x2 Pin Connector CONN HEADER VERT 30POS 2.54MM"
J3: "5x2 Pin connector"
L1: library part LED, "Red 631nm LED Indication - Discrete 2V 0603 (1608 Metric)"
R1 R3: library part "ERJ2G Resistor 0402", "Jumper 0.063W, 1/16W Chip Resistor 0402 (1005 Metric) Automotive AEC-Q200 Thick Film"
R2 R4 R15 R16 R19 R20 R24 R25 R29 R33 R34: library part "ERJ2G Resistor 0402", "Resistor 0402"
R5: library part "Resistor 0603", "120 kOhms ±0.1% 0.1W, 1/10W Chip Resistor 0603 (1608 Metric) Automotive AEC-Q200 Thin Film"
R6 R28: library part "Resistor 0603", "RES SMD 825 OHM 0.1% 1/10W 0603"
R7: library part "Resistor 0603", "22.6 kOhms ±0.1% 0.1W, 1/10W Chip Resistor 0603 (1608 Metric) Automotive AEC-Q200 Thin Film"
R8: library part "Resistor 0603", "16.5 kOhms ±0.1% 0.1W, 1/10W Chip Resistor 0603 (1608 Metric) Automotive AEC-Q200 Thin Film"
R9 R10: library part "ERJ2G Resistor 0402", "49.9 ±0.1% 0.063W, 1/16W Chip Resistor 0402 (1005 Metric) Automotive AEC-Q200 Thin Film"
R11 R13 R30: library part "ERJ2G Resistor 0402", "RES SMD 10K OHM 5% 1/10W 0402"
R12 R14 R38: library part "ERJ2G Resistor 0402", "RES SMD 1K OHM 5% 1/10W 0402"
R17: library part "Resistor 0603", "33 ±0.1% 0.1W, 1/10W Chip Resistor 0603 (1608 Metric) Automotive AEC-Q200 Thin Film"
R23: library part "ERJ2G Resistor 0402", "RES 15K OHM 1% 1/10W 0402 SMD"
R26: library part "Resistor 0603", "RES SMD 17.8K OHM 0.1% 1/5W 0603"
R27: library part "Resistor 0603", "RES SMD 130K OHM 0.1% 1/10W 0603"
R31: library part "ERJ2G Resistor 0402", "RES SMD 100K OHM 1% 1/10W 0402"
R32: library part "ERJ2G Resistor 0402", "RES, Thick Film, 4.99 kOhm, 1.0 %, 1/16 W, SMD, 0402"
R35: library part "Resistor 0603", "64.9 ±0.1% 0.2W, 1/5W Chip Resistor 0603 (1608 Metric) Automotive AEC-Q200, Pulse Withstanding Thick Film"
R36: library part "Resistor 0603", "RES SMD 45.3KOHM 0.1% 1/10W 0603"
R37: library part "Resistor 0603", "RES SMD 300 OHM 0.1% 1/10W 0603"
U1: library part "LTM4646IY 05-11-0399"
U2: library part LTM8033, "Non-Isolated PoL Module DC DC Converter Output 0.8 ~ 24V - - 3A 3.6V - 36V Input"
U3: library part LTM8045, "Non-Isolated PoL Module DC DC Converter Output -2.5 ~ -15V, 2.5 ~ 15V - - 700mA 2.8V - 18V Input"

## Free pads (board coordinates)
  round 3.81 hole 2.8: 1(4,4) 2(4,66) 3(66,66) 4(66,4)

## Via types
v1: diameter 0.508, hole 0.254, Top Layer to Bottom Layer, tented both sides, 382 vias

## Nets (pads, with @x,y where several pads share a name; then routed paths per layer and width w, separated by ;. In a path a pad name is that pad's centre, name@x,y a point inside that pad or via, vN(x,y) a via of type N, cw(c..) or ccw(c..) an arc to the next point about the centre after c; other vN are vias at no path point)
0.9V: C24.1 C25.1 C26.1 C27.1 C28.1 H1.1 J2.7 J2.8 J2.9 J2.10 R19.1 U1.H1 U1.J1 U1.J2 U1.K1 U1.K2 U1.L1 U1.L2 | length 30.4
  Top Layer w0.254: v1(46.558,40.792) U1.L2@47.193,40.157 U1.K2@48.463,40.157 ; v1(46.558,42.062) U1.L1@47.193,41.427 ; v1(47.828,40.792) U1.K2@48.463,40.157 ; v1(47.828,42.062) U1.K1@48.463,41.427 U1.J1@49.733,41.427 v1(49.098,42.062) ; v1(49.098,40.792) U1.J2@49.733,40.157 U1.K2@48.463,40.157
  Top Layer w0.508: U1.J1@49.733,41.427 U1.H1@51.003,41.427
  Signal w0.254: J2.8@51.403,63.752 52.579,64.928 60.421,64.928 61.087,64.262 61.087,61.253 H1.1@64.53,57.81
  Bottom Layer w0.254: v1(49.098,42.062) 49.827,42.062 R19.1@50.47,42.705
  other v1: 48.717,44.044 48.717,45.06 48.717,46.076 48.653,46.934 48.653,47.95 48.653,48.966 51.054,55.88 51.054,56.642 51.054,57.404 51.054,58.166
0.9V_PGood: J3.4 R12.1 | length 53.9
  Signal w0.178: J3.4@19.558,6.858 19.736,7.036 20.587,7.036 21.514,7.963 28.537,7.963 30.5,6 34,6 36,8 47.75,8 49,9.25 49,25.25 49.5,25.75 50.861,25.75 51.122,26.011 v1(52.489,26.011)
  Bottom Layer w0.178: v1@52.5,26.011 52.5,28.032 R12.1@52.502,28.034
2.2V: C20.1 C21.1 C22.1 C23.1 H2.1 J2.13 J2.14 J2.15 J2.16 U1.A1 U1.A2 U1.B1 U1.B2 U1.C1 U1.C2 U1.D1 U1.E2 | length 34.1
  Top Layer w0.254: U1.E2@54.813,40.157 v1(55.448,40.792) ; U1.C2@57.353,40.157 v1(57.988,40.792) ; U1.C1@57.353,41.427 v1(57.988,42.062) ; U1.B2@58.623,40.157 v1(59.258,40.792) ; U1.B1@58.623,41.427 v1(59.258,42.062) ; U1.A2@59.893,40.157 v1(60.528,40.792) ; U1.A1@59.893,41.427 v1(60.528,42.062)
  Top Layer w0.508: v1(55.448,40.792) U1.D1@56.083,41.427 U1.C1@57.353,41.427
  Signal w0.254: J2.13@43.783,66.643 J2.13@43.783,66.292 44.882,67.392 60.624,67.392 62.192,65.824 62.192,63.425 H2.1@64.555,61.062
  other v1: 60.96,43.993 60.96,45.009 60.96,46.025 61.015,47.648 61.015,48.664 40.945,55.524 40.945,56.413 40.945,57.252 40.919,58.09
2.2V_PGood: J3.9 R14.1 | length 59.7
  Signal w0.178: J3.9@19.558,4.318 19.609,4.267 20.587,4.267 21.64,3.213 28.016,3.213 29.781,4.978 33.635,4.978 33.694,4.919 50.669,4.919 51.75,6 51.75,24.25 52.5,25 55.744,25 v1(55.752,24.992)
  Bottom Layer w0.178: R14.1@55.593,28.194 55.593,25.157 v1@55.75,25
3.8VPGOOD: J3.5 R31.2 U2.B7 | length 33
  Top Layer w0.178: U2.B7@35.689,18.44 36.324,19.075 39.091,19.075 R31.2@39.522,19.507
  Top Layer w0.203: v1(35.079,19.05) U2.B7@35.689,18.44
  Signal w0.203: J3.5@17.018,6.858 17.125,6.965 18.085,6.965 19.527,8.407 27,8.407 28,9.407 28,16 29,17 34.5,17 35.079,17.579 v1(35.079,19.05)
  Bottom Layer w0.203: v1(35.079,19.05) v1@35.104,19.05
3.8VRUN: C33.1 R23.1 R24.1 R25.2 U2.G8 | length 16.6
  Top Layer w0.254: v1(29.313,16.332) 29.326,16.345 29.326,17.158 U2.G8@29.339,17.17
  Signal w0.178: v1(29.313,16.332) 29.313,8.634 30.937,7.01 v1@31.42,7.01
  Bottom Layer w0.178: v1(31.407,7.001) 31.407,6.134 C33.1@31.471,6.071 31.471,4.953 R25.2@31.801,4.623 31.656,4.478 R24.1@31.656,3.251 31.682,3.226 R23.1@32.944,3.226
+3.8V: C31.1 C32.1 H10.1 J2.19 J2.20 J2.21 J2.22 U2.A1 U2.A2 U2.A3 U2.B1 U2.B2 U2.B3 U2.C1 U2.C2 U2.C3 U2.D1 U2.D2 U2.D3 | length 32.2
  Top Layer w0.254: U2.D3@33.149,23.52 v1(33.784,24.155) ; U2.D2@33.149,24.79 v1(33.784,24.155) ; U2.D1@33.149,26.06 v1(33.784,25.425) ; U2.C3@34.419,23.52 v1(35.054,24.155) U2.B2@35.689,24.79 ; U2.C2@34.419,24.79 v1(33.784,24.155) ; U2.C1@34.419,26.06 35.003,25.476 v1(35.054,25.476) ; U2.B3@35.689,23.52 v1(36.324,24.155) ; U2.B1@35.689,26.06 36.273,25.476 36.349,25.476 36.933,26.06 U2.A1@36.959,26.06 ; U2.A3@36.959,23.52 v1(36.324,24.155) ; U2.A2@36.959,24.79 v1(36.324,24.155)
  Signal w0.178: H10.1@14.351,64.135 17.272,64.135 20.193,61.214 31.084,61.214 J2.22@33.623,63.752
  other v1: 37.814,24.102 37.814,25.372 36.37,25.467 35.083,26.848 33.75,26.896 36.29,26.896 37.814,26.896 36.019,28.524 36.019,29.439 36.019,30.251
-3.8V: C39.1 C40.1 H9.1 J2.25 J2.26 J2.27 J2.28 R37.1 U3.A4 U3.A5 U3.B4 U3.B5 | length 18.8
  Top Layer w0.178: U3.A5@27.534,46.634 27.534,48.843 27.814,49.124
  Signal w0.178: H9.1@11.125,64.135 12.522,65.532 16.891,65.532 17.399,65.024 24.731,65.024 J2.28@26.003,63.752
  other v1: 28.448,45.212 26.924,45.974 28.448,46.736 27.908,47.47 25.908,47.498 26.924,47.498 28.169,48.92 28.148,49.753 27.661,50.571 27.686,51.308 27.686,52.07
-3.8VRun: C37.1 R32.1 R33.1 R34.2 U3.G3 | length 10.6
  Top Layer w0.178: U3.G3@24.994,39.014 v1(25.629,38.379)
  Bottom Layer w0.178: R33.1@22.125,37.195 R33.1@22.047,37.117 22.047,38.329 22.733,39.014 24.994,39.014 v1(25.629,38.379) 25.629,38.304 25.476,38.151 C37.1@25.476,37.033 ; R34.2@25.205,35.763 25.476,36.035 C37.1@25.476,37.033 ; R32.1@26.975,37.059 26.949,37.033 C37.1@25.476,37.033
ADJ: R27.2 U2.A7 | length 3.1
  Top Layer w0.254: U2.A7@36.959,18.44 39.045,18.44 39.653,17.832 R27.2@39.778,17.832
BIAS: R31.1 U2.G3 U2.G4 | length 14.9
  Top Layer w0.254: v1(28.246,23.114) 28.256,23.114 28.663,23.52 U2.G3@29.339,23.52 U2.G4@29.339,22.25 ; v1(38.583,20.65) 38.605,20.629 39.501,20.629 R31.1@39.522,20.607
  Signal w0.254: v1(28.246,23.114) 29.034,22.327 36.832,22.327 38.508,20.65 v1(38.583,20.65) v1@38.659,20.65
ClockOUT: H8.1 U1.F4 | length 29.5
  Top Layer w0.254: v1(53.035,37.109) U1.F4@53.543,37.617
  Signal w0.178: v1(53.035,37.109) 52.375,36.449 52.375,35.375 54.367,33.383 54.367,33.367 54.788,32.947 54.788,31.212 v1@55,31 ; v1(55.002,30.992) 56.744,29.25 61.219,29.25 61.75,28.719 61.75,18.21 H8.1@63.96,16
COMP1: C18.1 U1.G1 U1.G3 | length 5.4
  Top Layer w0.254: v1(51.638,42.062) U1.G1@52.273,41.427 ; v1(51.765,39.395) U1.G3@52.273,38.887
  Bottom Layer w0.254: v1(51.638,42.062) 51.638,42.037 52.375,41.3 52.375,40.704 52.432,40.646 52.432,40.049 C18.1@52.705,39.776 52.432,39.503 51.942,39.503 51.834,39.395 v1(51.765,39.395)
COMP2: C19.1 U1.E1 U1.E3 | length 13.7
  Top Layer w0.254: U1.E3@54.813,38.887 v1(55.448,39.522) ; U1.E1@54.813,41.427 v1(55.448,42.062)
  Signal w0.178: v1(55.448,42.062) 56.286,42.901 62.431,42.901 62.431,42.869 62.548,42.752 v1(62.548,42.663)
  Signal w0.254: v1(55.448,39.522) 54.508,40.462 54.508,41.097 55.448,42.037 v1(55.448,42.062)
  Bottom Layer w0.178: v1(62.548,42.663) 62.548,43.574 C19.1@62.56,43.586
DRVCC: C15.1 U1.G7 | length 7.2
  Top Layer w0.254: v1(51.638,33.172) U1.G7@52.273,33.807
  Signal w0.178: v1@51.359,30.734 v1(51.333,30.734) 51.867,31.267 53.162,31.267 53.492,31.598 53.492,32.182 52.502,33.172 v1(51.638,33.172)
  Bottom Layer w0.178: C15.1@50.546,30.505 50.775,30.734 v1(51.333,30.734)
  Bottom Layer w0.254: v1(51.638,33.172) v1@51.701,33.172
EN_0.9V_SPARE: J3.8 R2.2 | length 50.5
  Signal w0.178: J3.8@22.098,4.318 22.098,4.348 23.084,5.334 23.114,5.334 23.368,5.588 33.528,5.588 33.841,5.275 50.522,5.275 51.25,6.003 v1@51.25,25
  Bottom Layer w0.178: v1(51.288,25.078) 51.288,26.261 R2.2@51.435,26.408
Enable_0V9: J1.09 R1.2 | length 32.9
  Signal w0.178: J1.09@36.207,6.379 37.328,7.5 48.318,7.5 49.993,9.175 v1(49.993,25.039)
  Bottom Layer w0.178: R1.2@49.116,26.746 49.116,25.917 v1(49.993,25.039)
FB: R36.2 U3.A3 | length 4.1
  Top Layer w0.178: R36.2@22.809,49.124 22.809,48.999 23.624,48.184 24.839,48.184 24.943,48.08 24.943,46.685 U3.A3@24.994,46.634
FIN: C34.1 U2.J8 U2.K8 U2.L8 | length 1.1
  Top Layer w0.254: U2.J8@26.799,17.17 26.799,16.459 27.027,16.231 v1(27.027,16.129)
  other v1: 19.839,16.078 20.728,16.078 21.617,16.078 23.59,16.228 24.86,16.228 26.13,16.228
FSET: R17.2 U1.F1 | length 2
  Top Layer w0.254: U1.F1@53.543,41.427 v1(53.543,42.062)
  Bottom Layer w0.254: v1(53.543,42.062) 53.592,42.014 53.592,41.56 54.129,41.022 R17.2@54.254,41.022
GND: C1.2 C2.2 C3.2 C4.2 C5.2 C6.2 C7.2 C8.2 C9.2 C14.2 C15.2 C20.2 C21.2 C22.2 C23.2 C24.2 C25.2 C26.2 C27.2 C28.2 C29.2 C30.2 C31.2 C32.2 C33.2 C34.2 C35.2 C36.2 C37.2 C38.2 C39.2 C40.2 C41.2 H1.2 H2.2 H3.2 H4.2 H5.2 H6.2 H7.2 H8.2 H9.2 H10.2 J1.01 J1.02 J1.07 J1.08 J2.5 J2.6 J2.11 J2.12 J2.17 J2.18 J2.23 J2.24 J2.29 J2.30 J3.1 J3.6 J3.10 L1.2 pad.1 pad.2 pad.3 pad.4 R20.1 R25.1 R26.1 R28.1 R30.1 R34.1 R35.1 U1.A3 U1.A6 U1.A7 U1.B3 U1.B6 U1.B7 U1.C3 U1.C4 U1.C5 U1.C6 U1.C7 U1.D6 U1.D7 U1.E6 U1.E8 U1.F5 U1.F7 U1.G6 U1.G8 U1.H6 U1.H7 U1.J4 U1.J5 U1.J6 U1.J7 U1.K3 U1.K6 U1.K7 U1.L3 U1.L6 U1.L7 U2.A4 U2.A5 U2.A8 U2.B4 U2.B5 U2.C4 U2.C5 U2.C6 U2.C7 U2.C8 U2.D4 U2.D5 U2.D6 U2.D7 U2.D8 U2.E1 U2.E2 U2.E3 U2.E4 U2.E5 U2.E6 U2.E7 U2.E8 U2.F1 U2.F2 U2.F3 U2.F4 U2.F5 U2.F6 U2.F7 U2.F8 U2.G1 U2.G2 U2.G5 U2.G6 U2.G7 U2.H5 U2.H6 U2.J5 U2.J6 U2.K5 U2.K6 U2.L5 U2.L6 U3.A1 U3.A2 U3.B1 U3.B2 U3.B3 U3.C1 U3.C2 U3.C3 U3.C4 U3.C5 U3.D1 U3.D2 U3.D3 U3.D4 U3.D5 U3.E1 U3.E2 U3.E3 U3.E4 U3.E5 U3.F2 U3.F3 U3.F4 U3.F5 U3.G2 U3.H1 U3.H2 U3.H3 | length 138.9
  Top Layer w0.254: v1(1.837,1.837) 2.028,1.837 2.752,2.561 ; v1(2,7) 2,6.931 pad.1@3.869,5.063 ; 3.869,6.731 pad.1@3.869,5.063 ; 4,5.905 pad.1@4,4.453 ; R35.1@20.523,37.44 22.004,37.44 22.309,37.744 U3.H1@22.454,37.744 v1(23.089,38.379) ; C38.2@20.523,41.783 20.752,41.554 U3.E1@22.454,41.554 v1(23.089,40.919) ; U3.D1@22.454,42.824 v1(23.089,42.189) U3.D2@23.724,42.824 ; U3.C1@22.454,44.094 v1(23.089,43.459) ; U3.B1@22.454,45.364 v1(23.089,44.729) ; U3.A1@22.454,46.634 v1(23.089,45.999) U3.A2@23.724,46.634 ; U3.H2@23.724,37.744 v1(23.089,38.379) ; U3.F2@23.724,40.284 v1(24.359,39.649) U3.F3@24.994,40.284 ; U3.E2@23.724,41.554 v1(24.359,40.919) ; U3.C2@23.724,44.094 v1(24.359,43.459) ; U3.B2@23.724,45.364 v1(24.359,44.729) U3.B3@24.994,45.364 ; U2.L6@24.259,19.71 24.843,19.126 v1(24.894,19.126) ; U2.L5@24.259,20.98 24.843,20.396 v1(24.894,20.396) 24.944,20.396 U2.K5@25.529,20.98 ; v1(24.359,42.189) U3.D3@24.994,42.824 ; U3.H3@24.994,37.744 v1(24.359,38.379) U3.G2@23.724,39.014 v1(23.089,38.379) ; U3.E3@24.994,41.554 v1(25.629,40.919) ; U3.C3@24.994,44.094 v1(25.629,43.459) ; U2.K6@25.529,19.71 26.113,19.126 v1(26.164,19.126) ; v1(25.629,39.649) U3.F4@26.264,40.284 ; v1(25.629,42.189) U3.D4@26.264,42.824 ; v1(26.164,20.396) 26.214,20.396 U2.J5@26.799,20.98 ; U3.E4@26.264,41.554 v1(26.899,40.919) U3.E5@27.534,41.554 ; U3.C4@26.264,44.094 v1(26.899,43.459) U3.C5@27.534,44.094 ; U2.J6@26.799,19.71 27.383,19.126 v1(27.434,19.126) ; v1(26.899,39.649) U3.F5@27.534,40.284 ; v1(26.899,42.189) U3.D5@27.534,42.824 ; v1(27.434,20.396) 27.484,20.396 U2.H5@28.069,20.98 ; U2.H6@28.069,19.71 v1(28.704,19.075) ; v1(28.704,20.345) U2.G5@29.339,20.98 ; U2.G7@29.339,18.44 v1(29.974,17.805) ; U2.G6@29.339,19.71 v1(29.974,19.075) ; U2.G2@29.339,24.79 29.923,24.206 v1(29.974,24.206) ; U2.G1@29.339,26.06 29.969,25.43 v1(29.974,25.43) ; v1(29.974,20.345) U2.F5@30.609,20.98 ; U2.F8@30.609,17.17 30.609,16.51 30.837,16.281 ; U2.F7@30.609,18.44 v1(31.244,17.805) ; U2.F6@30.609,19.71 v1(31.244,19.075) ; U2.F4@30.609,22.25 31.23,21.629 v1(31.233,21.629) ; U2.F3@30.609,23.52 31.103,23.026 31.384,23.026 U2.E3@31.879,23.52 ; U2.F2@30.609,24.79 v1(31.218,24.181) 31.269,24.181 U2.E2@31.879,24.79 ; U2.F1@30.609,26.06 v1(31.244,25.425) U2.E1@31.879,26.06 ; v1(31.244,20.345) U2.E5@31.879,20.98 ; U2.E8@31.879,17.17 31.879,16.463 31.98,16.362 v1(31.98,16.307) ; U2.E7@31.879,18.44 v1(32.514,17.805) ; U2.E6@31.879,19.71 v1(32.514,19.075) ; U2.E4@31.879,22.25 32.463,21.666 v1(32.514,21.666) ; v1(32.514,20.345) U2.D5@33.149,20.98 ; U2.D8@33.149,17.17 33.149,16.463 33.25,16.362 v1(33.25,16.307) ; U2.D7@33.149,18.44 v1(33.784,17.805) U2.C7@34.419,18.44 ; U2.D6@33.149,19.71 v1(33.784,19.075) ; U2.D4@33.149,22.25 33.758,21.641 v1(33.784,21.641) ; v1(34.403,16.236) 34.411,16.244 34.411,17.163 U2.C8@34.419,17.17 ; U2.C6@34.419,19.71 v1(33.784,20.345) U2.C5@34.419,20.98 ; U2.C4@34.419,22.25 35.003,21.666 v1(35.054,21.666) ; U2.B5@35.689,20.98 36.298,21.59 v1(36.298,21.641) ; U2.B4@35.689,22.25 v1(36.298,21.641) ; U2.A8@36.959,17.17 37.529,16.6 37.529,16.371 v1(37.568,16.332) 37.568,16.263 37.77,16.062 R30.1@37.77,14.884 ; U2.A4@36.959,22.25 36.349,21.641 v1(36.298,21.641) ; v1(40.894,34.76) 41.796,34.76 C8.2@41.859,34.823 ; v1(46.558,33.172) U1.L7@47.193,33.807 ; v1(46.558,34.442) U1.L6@47.193,35.077 ; v1(46.558,38.887) U1.L3@47.193,38.887 ; v1(47.828,33.172) U1.K7@48.463,33.807 ; v1(47.828,34.442) U1.K6@48.463,35.077 ; v1(47.828,38.887) U1.K3@48.463,38.887 ; v1(49.098,33.172) U1.J7@49.733,33.807 ; v1(49.098,34.442) U1.J6@49.733,35.077 U1.J5@49.733,36.347 49.733,37.236 ; v1(50.368,33.172) U1.H7@51.003,33.807 ; v1(50.368,34.442) U1.H6@51.003,35.077 ; v1(51.638,34.442) U1.G6@52.273,35.077 ; U1.F5@53.543,36.347 U1.E6@54.813,35.077 U1.D6@56.083,35.077 v1(56.718,34.442) ; U1.E8@54.813,32.537 54.82,32.537 55.455,31.902 v1(55.461,31.902) ; U1.D7@56.083,33.807 v1(56.718,33.172) ; U1.C7@57.353,33.807 v1(57.988,33.172) ; U1.C5@57.353,36.347 U1.C6@57.353,35.077 v1(57.988,34.442) ; U1.C4@57.571,37.836 v1(57.988,38.252) ; U1.B7@58.623,33.807 v1(59.258,33.172) ; U1.B6@58.623,35.077 58.642,35.077 59.277,34.442 v1(59.296,34.442) ; U1.A7@59.893,33.807 59.9,33.807 60.535,33.172 v1(60.541,33.172) ; U1.A6@59.893,35.077 v1(60.528,35.077) ; pad.4@65.655,4.195 68.019,1.831 v1(68.019,1.702) ; v1(67.208,36.017) 66.815,36.411 C2.2@66.307,36.411 ; v1(67.234,37.033) 66.929,37.033 C2.2@66.307,36.411 ; v1(67.234,37.821) 66.307,36.893 C2.2@66.307,36.411 ; 2.752,2.561 4,3.809 pad.1@4,4.131 ; 2.752,2.561 pad.1@4.322,4.131 ; pad.1@3.869,4.584 pad.1@3.869,5.063 ; pad.1@3.869,4.584 pad.1@4,4.453 ; pad.1@3.869,4.584 3.869,4.262 pad.1@4,4.131 ; pad.1@4,4.131 pad.1@4.322,4.131 ; pad.1@4,4.131 pad.1@4,4.453 ; pad.1@4,4.453 pad.1@4.322,4.131
  Top Layer w0.508: U1.K3@48.463,38.887 49.468,37.882 49.468,37.236 ; v1(51.638,31.902) U1.G8@52.273,32.537 U1.F7@53.543,33.807 ; U1.C5@57.353,36.347 57.396,36.39 57.396,36.69 57.404,36.698 57.404,37.617 57.404,37.789 U1.C4@57.511,37.896
  Top Layer w0.762: U1.C4@57.531,37.916 57.531,38.589 57.353,38.767 U1.C3@57.353,38.887 U1.B3@58.623,38.887 U1.A3@59.893,38.887 v1(60.528,38.887)
  Signal w0.254: pad.4@65.75,4.25 pad.4@66,4
  Bottom Layer w0.178: v1@50.19,27.838 50.546,28.194 C15.2@50.546,28.905
  Bottom Layer w0.254: v1(23.089,38.379) 23.127,38.341 23.127,37.782 C37.2@23.876,37.033 24.105,36.805 R34.1@24.105,35.763 ; R25.1@32.901,4.623 32.901,5.901 C33.2@33.071,6.071 v1@33.071,7.264 ; R20.1@43.783,39.173 43.764,39.192 46.185,39.192 46.489,38.887 v1(46.558,38.887) ; v1@51.59,31.854 v1(51.638,31.902) ; v1(51.638,34.442) v1@51.707,34.442 ; C14.2@55.651,35.382 55.924,35.655 56.592,35.655 56.649,35.712 v1(56.718,35.712)
  other v1: 7,2 12,2 17,2 22,2 27,2 32,2 37,2 42,2 47,2 52,2 57,2 62,2 68,7 33.073,7.262 2,12 68,12 56.527,15.946 56.527,16.708 2,17 68,17 56.527,17.47 56.527,18.232 56.527,20.518 56.527,21.28 19.839,21.666 20.728,21.666 21.617,21.666 24.86,21.816 26.13,21.816 27.432,21.844 2,22 68,22 56.527,22.042 56.527,22.804 31.244,22.987 2,27 68,27 50.202,27.895 30.583,28.524 30.583,29.439 30.583,30.251 39.853,31.902 2,32 68,32 39.853,32.791 39.853,33.68 65.786,34.722 39.827,36.093 20.527,36.645 39.827,36.982 2,37 68,37 39.827,37.871 31.964,41.94 32.726,41.94 29.156,41.956 30.172,41.956 31.188,41.956 2,42 68,42 20.474,42.63 54.331,43.967 55.22,43.967 54.331,44.983 55.22,44.983 54.331,45.999 55.22,45.999 55.332,46.766 54.331,46.787 2,47 68,47 23.082,47.216 55.332,47.782 54.331,47.803 55.332,48.798 54.331,48.819 21.971,50.292 21.971,51.181 2,52 68,52 21.971,52.07 47.142,55.55 53.813,55.634 53.848,56.388 47.142,56.413 2,57 68,57 53.848,57.15 47.168,57.404 53.848,57.912 47.168,58.318 2,62 68,62 7,68 12,68 17,68 22,68 27,68 32,68 37,68 42,68 47,68 52,68 57,68 62,68
INTVCC: C14.1 R9.2 R10.2 R11.2 R13.2 U1.D2 U1.F3 U1.F6 | length 38.4
  Top Layer w0.254: v1(53.035,35.712) U1.F6@53.543,35.077 ; U1.F3@53.543,38.887 v1(54.051,38.379) ; U1.D2@56.083,40.157 v1(56.591,39.776)
  Signal w0.178: v1(55.002,29.742) 56.245,28.499 v1@61.062,28.499 ; v1@56.058,31 56.058,32.442 55.233,33.267 55.233,34.267 53.788,35.712 v1(53.035,35.712) 53.698,36.375 53.698,36.523 53.696,36.525 53.696,37.999 54.051,38.354 v1(54.051,38.379) 54.127,38.379 54.457,38.71 55.524,38.71 v1(56.591,39.776)
  Signal w0.254: v1(45.51,29.788) v1@55.108,29.788
  Bottom Layer w0.178: R11.2@53.823,28.727 54.864,28.727 R13.2@55.626,29.489 ; R13.2@55.559,29.556 55.559,30.492 v1(56.06,30.992) ; R10.2@61.011,29.304 61.064,29.251 v1(61.064,28.561)
  Bottom Layer w0.254: v1@45.491,29.769 v1(45.51,29.788) 45.585,29.863 R9.2@46.482,29.863 ; v1(53.035,35.712) 53.104,35.712 53.161,35.655 53.778,35.655 C14.1@54.051,35.382 ; v1(55.002,29.742) 55.071,29.742 55.15,29.662 55.453,29.662 55.559,29.556 R13.2@55.626,29.489
MEZZ_EN: J1.10 R3.2 R23.2 R32.2 | length 80
  Signal w0.178: v1(26.923,35.01) 34.49,35.01 41.75,27.75 47.779,27.75 ; v1(34.252,7.492) 35.259,8.5 47.5,8.5 48,9 48,26.471 48.529,27 ; 47.75,27.721 47.779,27.75 ; v1(59.959,25.058) 59.901,25 57.5,25 55.728,26.772 51.272,26.772 50.75,26.25 49.279,26.25 48.529,27 ; 47.779,27.75 48.529,27
  Bottom Layer w0.178: v1@26.924,35.001 26.975,35.052 R32.2@26.975,35.959 R32.2@26.983,35.951 ; R23.2@34.222,3.488 R23.2@34.011,3.277 35.423,3.277 35.985,3.839 J1.10@36.207,3.839 34.25,5.795 v1@34.25,7.5 ; v1@60,25 60.046,25.046 R3.2@60.046,26.492
MEZZ_EN_SPARE: J3.3 R4.2 R24.2 R33.2 | length 114.4
  Signal w0.178: v1(22.022,35.052) 22.72,35.75 34.5,35.75 42.055,28.195 47.945,28.195 49.321,26.818 50.679,26.818 51.064,27.203 56.25,27.203 57.722,25.731 v1(57.722,25.719) ; J3.3@22.098,6.858 20.99,5.75 18.75,5.75 18.324,5.324 18.324,3.75 19.324,2.75 31.624,2.75 ; v1(30.01,4.363) 31.624,2.75 ; v1(58.613,24.271) 53.271,24.271 52.25,23.25 52.25,5 50,2.75 31.624,2.75
  Bottom Layer w0.178: v1(22.022,35.052) 22.047,35.077 R33.2@22.047,36.017 R33.2@22.088,35.976 ; v1@30.023,4.369 30.023,3.962 R24.2@30.556,3.429 ; R24.2@30.556,3.251 R24.2@30.564,3.243 ; v1(57.722,25.719) 58.544,25.719 58.598,25.773 ; v1@57.75,25.75 v1@57.773,25.773 ; v1@58.5,24.25 58.598,24.348 58.598,25.773 ; R4.2@58.623,26.459 58.598,26.434 58.598,25.773
NetC16_1: C16.1 R15.1 | length 1.6
  Bottom Layer w0.254: C16.1@47.854,29.007 48.565,29.007 R15.1@49.2,29.642
NetC17_1: C17.1 R16.1 | length 1.7
  Bottom Layer w0.254: R16.1@58.039,29.761 58.707,29.761 C17.1@59.461,29.007
NetD2_2: D2.2 J1.03 J1.04 J1.05 J1.06
  other v1: 42.672,10.16 42.672,11.176
NetD3_2: D3.2 J3.2 J3.7
NetL1_1: L1.1 R38.2 | length 3
  Top Layer w0.178: R38.2@60.63,2.405 61.46,2.405 61.709,2.654 61.709,3.162 v1(61.722,3.175)
  Bottom Layer w0.178: L1.1@60.655,3.746 60.947,3.454 61.353,3.454 61.633,3.175 v1(61.722,3.175)
NetR5_1: R5.1 R6.2 | length 1.9
  Bottom Layer w0.254: R6.2@40.894,40.64 40.957,40.703 40.957,42.405 R5.1@41.021,42.469
NetR27_1: R27.1 R28.2 | length 2.4
  Top Layer w0.178: R28.2@39.414,14.295 39.7,14.582 R28.2@39.7,14.707 39.7,16.13 39.903,16.332 R27.1@39.778,16.332
NetR36_1: R36.1 R37.2 | length 1.1
  Top Layer w0.178: R36.1@24.309,49.124 R37.2@25.451,49.124
PGOOD1: R11.1 R12.2 U1.G5 | length 10
  Top Layer w0.254: v1(51.765,35.839) U1.G5@52.273,36.347
  Signal w0.178: v1(51.765,35.839) 51.765,35.242 52.25,34.758 52.25,34.305 52.354,34.201 52.923,34.201 54.356,32.768 54.356,30.81 v1@54.102,30.556
  Bottom Layer w0.178: R12.2@52.502,29.134 53.129,29.134 R11.1@53.823,29.827 53.823,30.322 v1(54.114,30.613)
PGOOD2: R13.1 R14.2 U1.E5 | length 11.3
  Top Layer w0.254: v1(54.305,36.855) U1.E5@54.813,36.347
  Signal w0.178: v1(54.305,36.855) 54.305,36.055 56.11,34.25 56.11,34.206 56.471,33.846 57.146,33.846 57.315,33.676 57.315,30.944 v1(56.679,30.308)
  Bottom Layer w0.178: v1(56.679,30.308) 56.679,29.536 56.693,29.523 R14.2@56.693,28.194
